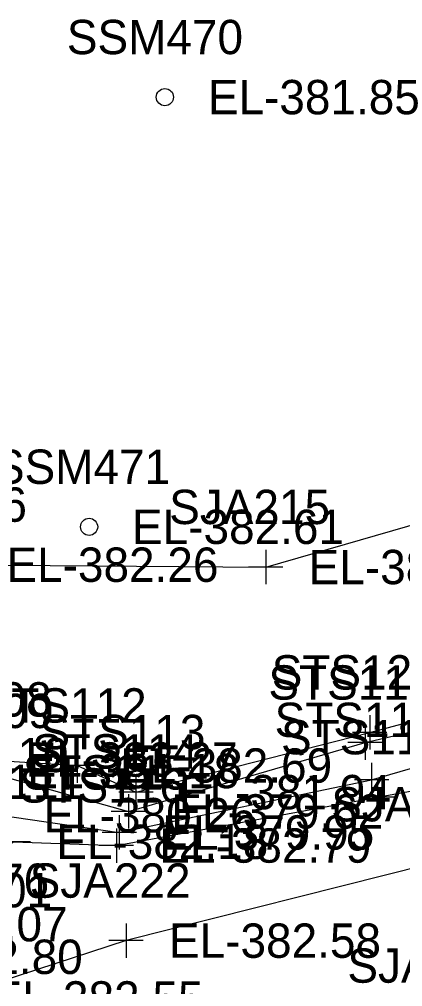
# Model space of a CAD drawing. Extents: x 1189978 to 1314812, y 571533 to 629339.
# Drawn here: x 1217741.2 to 1217785.8, y 622040.1 to 622152.8 of the extents above; entities that cross this region are included whole.
import ezdxf

# ---------------------------------------------------------------- set-up
doc = ezdxf.new("R2010")
doc.units = 0
for name, color, linetype in [('SURVEY - DTM - Breaklines', 7, 'Continuous'), ('SURVEY - DTM - Breaklines - Points - Elevations', 7, 'Continuous'), ('SURVEY - DTM - Breaklines - Points - Locators', 7, 'Continuous'), ('SURVEY - DTM - Breaklines - Points - Numbers', 7, 'Continuous'), ('SURVEY - DTM - Spot Points - Elevations', 7, 'Continuous'), ('SURVEY - DTM - Spot Points - Locators', 7, 'Continuous'), ('SURVEY - DTM - Spot Points - Point Numbers', 7, 'Continuous'), ('SURVEY - VEGETATION - Features - Points - Elevations', 7, 'Continuous'), ('SURVEY - VEGETATION - Features - Points - Locators', 7, 'Continuous'), ('SURVEY - VEGETATION - Features - Points - Numbers', 7, 'Continuous'), ('SURVEY - VEGETATION - Features with Text', 7, 'Continuous')]:
    doc.layers.add(name, color=color, linetype=linetype)

msp = doc.modelspace()

# ---------------------------------------------------------------- linework, layer by layer
at = {"layer": 'SURVEY - DTM - Breaklines'}
for points in [[(1217698.9, 622055.52), (1217707.68, 622051.88), (1217714.98, 622052.47), (1217736.91, 622066.59), (1217747.93, 622065.89), (1217754.77, 622062.79), (1217782, 622069.74), (1217810.4, 622077.34)], [(1217699.98, 622049.72), (1217707.39, 622049.09), (1217715.32, 622051.37), (1217737.11, 622065.25), (1217753.89, 622060.54), (1217781.44, 622068.56), (1217808.88, 622074.94)], [(1217697.47, 622046.01), (1217708.67, 622045.75), (1217717.12, 622047.41), (1217739, 622060.11), (1217752.83, 622058.09), (1217782.2, 622064.21), (1217807.7, 622071.64)], [(1217688.16, 622042.74), (1217698.41, 622043.14), (1217710.47, 622042.57), (1217718.89, 622043.61), (1217740.49, 622057), (1217752.49, 622056.57), (1217782.9, 622062.19), (1217807.59, 622066.7)]]:
    msp.add_lwpolyline(points, dxfattribs=at)
at = {"layer": 'SURVEY - DTM - Breaklines - Points - Locators'}
for p, q in [((1217782, 622071.74), (1217782, 622067.74)), ((1217781.44, 622070.56), (1217781.44, 622066.56)), ((1217784, 622069.74), (1217780, 622069.74)), ((1217747.93, 622067.89), (1217747.93, 622063.89)), ((1217783.44, 622068.56), (1217779.44, 622068.56)), ((1217749.93, 622065.89), (1217745.93, 622065.89)), ((1217782.2, 622066.21), (1217782.2, 622062.21)), ((1217754.77, 622064.79), (1217754.77, 622060.79)), ((1217784.2, 622064.21), (1217780.2, 622064.21)), ((1217782.9, 622064.19), (1217782.9, 622060.19)), ((1217756.77, 622062.79), (1217752.77, 622062.79)), ((1217753.89, 622062.54), (1217753.89, 622058.54)), ((1217784.9, 622062.19), (1217780.9, 622062.19)), ((1217755.89, 622060.54), (1217751.89, 622060.54)), ((1217752.83, 622060.09), (1217752.83, 622056.09)), ((1217754.83, 622058.09), (1217750.83, 622058.09)), ((1217752.49, 622058.57), (1217752.49, 622054.57)), ((1217742.49, 622057), (1217738.49, 622057)), ((1217754.49, 622056.57), (1217750.49, 622056.57))]:
    msp.add_line(p, q, dxfattribs=at)
at = {"layer": 'SURVEY - DTM - Spot Points - Locators'}
for centre in [(1217758.14, 622143.74), (1217749.31, 622093.69)]:
    msp.add_circle(centre, 1, dxfattribs=at)
at = {"layer": 'SURVEY - VEGETATION - Features - Points - Locators'}
for p, q in [((1217769.88, 622091.01), (1217769.88, 622087.01)), ((1217771.88, 622089.01), (1217767.88, 622089.01)), ((1217753.62, 622047.49), (1217753.62, 622043.49)), ((1217755.62, 622045.49), (1217751.62, 622045.49))]:
    msp.add_line(p, q, dxfattribs=at)
at = {"layer": 'SURVEY - VEGETATION - Features with Text'}
msp.add_lwpolyline([(1217809.21, 622052.52), (1217788.75, 622054.38), (1217753.62, 622045.49), (1217732.95, 622038.76), (1217711.59, 622023.66), (1217699.22, 622025.69), (1217697.28, 622056.62), (1217710.52, 622083.06), (1217734.69, 622089.28), (1217769.88, 622089.01), (1217801.2, 622098.03)], dxfattribs=at)

# ---------------------------------------------------------------- texts
at = {"layer": 'SURVEY - DTM - Breaklines - Points - Elevations'}
for s, p in [('EL-383.27', (1217741.91, 622064.59)), ('EL-382.69', (1217752.93, 622063.89)), ('EL-381.18', (1217742.11, 622063.25)), ('EL-381.94', (1217759.77, 622060.79)), ('EL-379.62', (1217758.89, 622058.54)), ('EL-380.26', (1217744, 622058.11)), ('EL-379.95', (1217757.83, 622056.09)), ('EL-382.18', (1217745.49, 622055)), ('EL-382.79', (1217757.49, 622054.57)), ('EL-381.76', (1217719.98, 622050.47)), ('EL-381.01', (1217720.32, 622049.37)), ('EL-380.07', (1217722.12, 622045.41)), ('EL-382.80', (1217723.89, 622041.61))]:
    msp.add_text(s, height=4, dxfattribs=at).set_placement(p)
at = {"layer": 'SURVEY - DTM - Breaklines - Points - Numbers'}
for s, p in [('STS120', (1217770.58, 622074.74)), ('STS119', (1217770.19, 622073.56)), ('STS108', (1217725.62, 622071.59)), ('STS112', (1217736.69, 622070.89)), ('STS109', (1217725.85, 622070.25)), ('STS118', (1217770.91, 622069.21)), ('STS113', (1217743.53, 622067.79)), ('STS117', (1217771.66, 622067.19)), ('STS110', (1217727.59, 622065.11)), ('STS114', (1217742.65, 622065.54)), ('STS115', (1217741.59, 622063.09)), ('STS111', (1217729.4, 622062)), ('STS116', (1217741.14, 622061.57))]:
    msp.add_text(s, height=4, dxfattribs=at).set_placement(p)
at = {"layer": 'SURVEY - DTM - Spot Points - Elevations'}
for s, p in [('EL-381.85', (1217763.14, 622141.74)), ('EL-382.61', (1217754.31, 622091.69))]:
    msp.add_text(s, height=4, dxfattribs=at).set_placement(p)
at = {"layer": 'SURVEY - DTM - Spot Points - Point Numbers'}
for s, p in [('SSM470', (1217746.72, 622148.74)), ('SSM471', (1217738.23, 622098.69)), ('SJA225', (1217779.39, 622040.59))]:
    msp.add_text(s, height=4, dxfattribs=at).set_placement(p)
at = {"layer": 'SURVEY - VEGETATION - Features - Points - Elevations'}
for s, p in [('EL-382.26', (1217739.69, 622087.28)), ('EL-382.96', (1217774.88, 622087.01)), ('EL-382.58', (1217758.62, 622043.49)), ('EL-382.55', (1217737.95, 622036.76))]:
    msp.add_text(s, height=4, dxfattribs=at).set_placement(p)
at = {"layer": 'SURVEY - VEGETATION - Features - Points - Numbers'}
for s, p in [('SJA216', (1217723.34, 622094.28)), ('SJA215', (1217758.64, 622094.01)), ('SJA223', (1217777.51, 622059.38)), ('SJA222', (1217742.39, 622050.49))]:
    msp.add_text(s, height=4, dxfattribs=at).set_placement(p)

doc.saveas('drawing.dxf')
